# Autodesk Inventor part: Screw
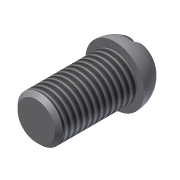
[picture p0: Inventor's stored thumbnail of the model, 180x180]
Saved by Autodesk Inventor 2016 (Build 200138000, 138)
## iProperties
Shininess: 77.0
Length Units: 11269
Angle Units: 11279
Time Units: 11290
Mass Units: 11283
Length Display Precision: 3
Angle Display Precision: 2
Created: 2002-01
Part Number: Screw
Document SubType Name: Modeling
Designer: ***
Density: 1 g/cm^3
Material: Generic
Appearance: Default
Density: 0.0
Volumn: 0.0
Area: 0.0
PropertySet Name: Model Information
Control State: 0
Master: False
Checked Out: False
Author: ***
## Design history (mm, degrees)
sketch "Sketch1"
  geometry: L1 (-0.061, 13.328)-(-0.061, -1.672); L2 (-0.061, -1.672)-(14.939, -1.672); A1 r 15 centre (-0.061, -1.672) between (14.939, -1.672) and (-0.061, 13.328)
  constraints: 4 end point, 2 point on circle, 1 centre point
  dimensions: "d0" = 15 radius of A1
revolve "Revolution1" sketch "Sketch1" stored, may be unused: angle "d3" = 90 deg
workplane "Work Plane2"
sketch "Sketch3"
  geometry: L1 (-3, 26)-(3, 26); L2 (3, 26)-(3, 6); L3 (3, 6)-(-3, 6); L4 (-3, 6)-(-3, 26); L5 (-15, 0)-(15, 0) reference
  constraints: 8 end point, 2 parallel, 1 horizontal, 1 perpendicular
  dimensions: "d11" = 6 distance of L1.start L1.end; "d12" = 20 distance of L3.end L1.start; "d13" = 6 distance between parallel lines of L5 L3; "d14" = 12 distance from line of L4 L5.start
extrude "Extrusion2" cut sketch "Sketch3" stored distance "d15" = 10; taper "d16" = 0 deg
sketch "Sketch4"
  geometry: C1 r 11.5 at (0, 0); C2 r 15 at (0, 0) reference
  constraints: 1 centre point, 1 concentric
  dimensions: "d17" = 23 diameter of C1
extrude "Extrusion3" join sketch "Sketch4" distance "d18" = 40; taper "d19" = 0 deg
chamfer "Chamfer1" distance "d20" = 2; stored, may be unused: second distance "d21" = 2, angle "d24" = 45 deg
thread "Thread1" dims "d22" = 10, "d23" = 0
body "Solid1"
